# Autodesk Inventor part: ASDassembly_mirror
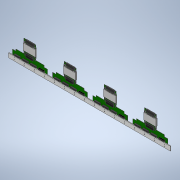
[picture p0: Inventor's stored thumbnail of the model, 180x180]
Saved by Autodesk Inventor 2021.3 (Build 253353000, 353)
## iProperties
Created: 2021-12
Part Number: ASDassembly_mirror
Material: 一般
Document SubType Name: Modeling
Designer: kengo
Density: 1 g/cm^3
Appearance: 既定
Author: kengo
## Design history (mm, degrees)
derived "ASDaeembly.iam"
node "ソリッド1"
node "ASD_frame.ipt:1"
node "ASD_adaptor.ipt:1"
node "ソリッド2"
node "ASD_adaptor.ipt:2"
node "ソリッド3"
node "ASD_adaptor.ipt:3"
node "ソリッド4"
node "ASD_adaptor.ipt:4"
node "ソリッド5"
node "ASDcard.ipt:1"
node "ソリッド6"
node "ASDcard.ipt:2"
node "ソリッド7"
node "ASDcard.ipt:3"
node "ソリッド8"
node "ASDcard.ipt:4"
node "ソリッド9"
